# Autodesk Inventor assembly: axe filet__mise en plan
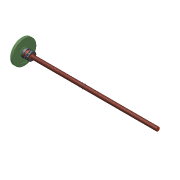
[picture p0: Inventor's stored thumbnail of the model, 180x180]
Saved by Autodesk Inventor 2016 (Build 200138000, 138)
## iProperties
Created: 2011-10
Part Number: axe filet__mise en plan
Document SubType Name: Assembly
Designer: Bruno
Mass: 63.1086 g
Surface Area: 297.166 cm^2
Volume: 63.1086 cm^3
Density: 1 g/cm^3
Author: Bruno
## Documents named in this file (8)
- C:\Users\uhl\Desktop\Cric-Inventor\axe filet__mise en plan.iam
- C:\Users\uhl\Desktop\Cric-Inventor\Roulement_r1rb26_D_faut.iam
- C:\Users\uhl\Desktop\Cric-Inventor\roue Z68_mise en plan.ipt
- C:\Users\uhl\Desktop\Cric-Inventor\Clavette 4x4x6_D_faut.ipt
- C:\Users\uhl\Desktop\Cric-Inventor\axe filet__D_faut.ipt
- C:\Users\uhl\Desktop\Cric-Inventor\segment d''arr_t diam 12_D_faut.ipt
- C:\Users\uhl\Desktop\Cric-Inventor\Roulement_b1rb8_D_faut.iam
- C:\Users\uhl\Desktop\Cric-Inventor\Segment d''arr_t diam 11_D_faut.ipt
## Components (7 placed, 7 different names)
1. Roulement_r1rb26_D_faut:1 [sub-assembly] — Logement:1
2. roue Z68_mise en plan:1 — Plaquage:1, Plaquage:8, Plaquage:9, Plaquage:10
3. Clavette 4x4x6_D_faut:1 — Plaquage:3, Plaquage:4, Plaquage:5, Plaquage:9
4. axe filet__D_faut:1 — Plaquage:1, Plaquage:3, Plaquage:4, Plaquage:5, Plaquage:6, Logement:1, Plaquage:7, Plaquage:8, Plaquage:10, Logement:2
5. segment d''arr_t diam 12_D_faut:1 — Plaquage:7
6. Roulement_b1rb8_D_faut:1 [sub-assembly] — Logement:2
7. Segment d''arr_t diam 11_D_faut:1 — Plaquage:6
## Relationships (11: Mate 9, Insert 2)
- Plaquage:1 [Mate]: roue Z68_mise en plan:1 ↔ axe filet__D_faut:1
- Plaquage:3 [Mate]: Clavette 4x4x6_D_faut:1 ↔ axe filet__D_faut:1
- Plaquage:4 [Mate]: Clavette 4x4x6_D_faut:1 ↔ axe filet__D_faut:1
- Plaquage:5 [Mate]: Clavette 4x4x6_D_faut:1 ↔ axe filet__D_faut:1
- Plaquage:6 [Mate]: axe filet__D_faut:1 ↔ Segment d''arr_t diam 11_D_faut:1
- Logement:1 [Insert]: Roulement_r1rb26_D_faut:1 ↔ axe filet__D_faut:1
- Plaquage:7 [Mate]: axe filet__D_faut:1 ↔ segment d''arr_t diam 12_D_faut:1
- Plaquage:8 [Mate]: roue Z68_mise en plan:1 ↔ axe filet__D_faut:1
- Plaquage:9 [Mate]: roue Z68_mise en plan:1 ↔ Clavette 4x4x6_D_faut:1
- Plaquage:10 [Mate]: roue Z68_mise en plan:1 ↔ axe filet__D_faut:1
- Logement:2 [Insert]: axe filet__D_faut:1 ↔ Roulement_b1rb8_D_faut:1
